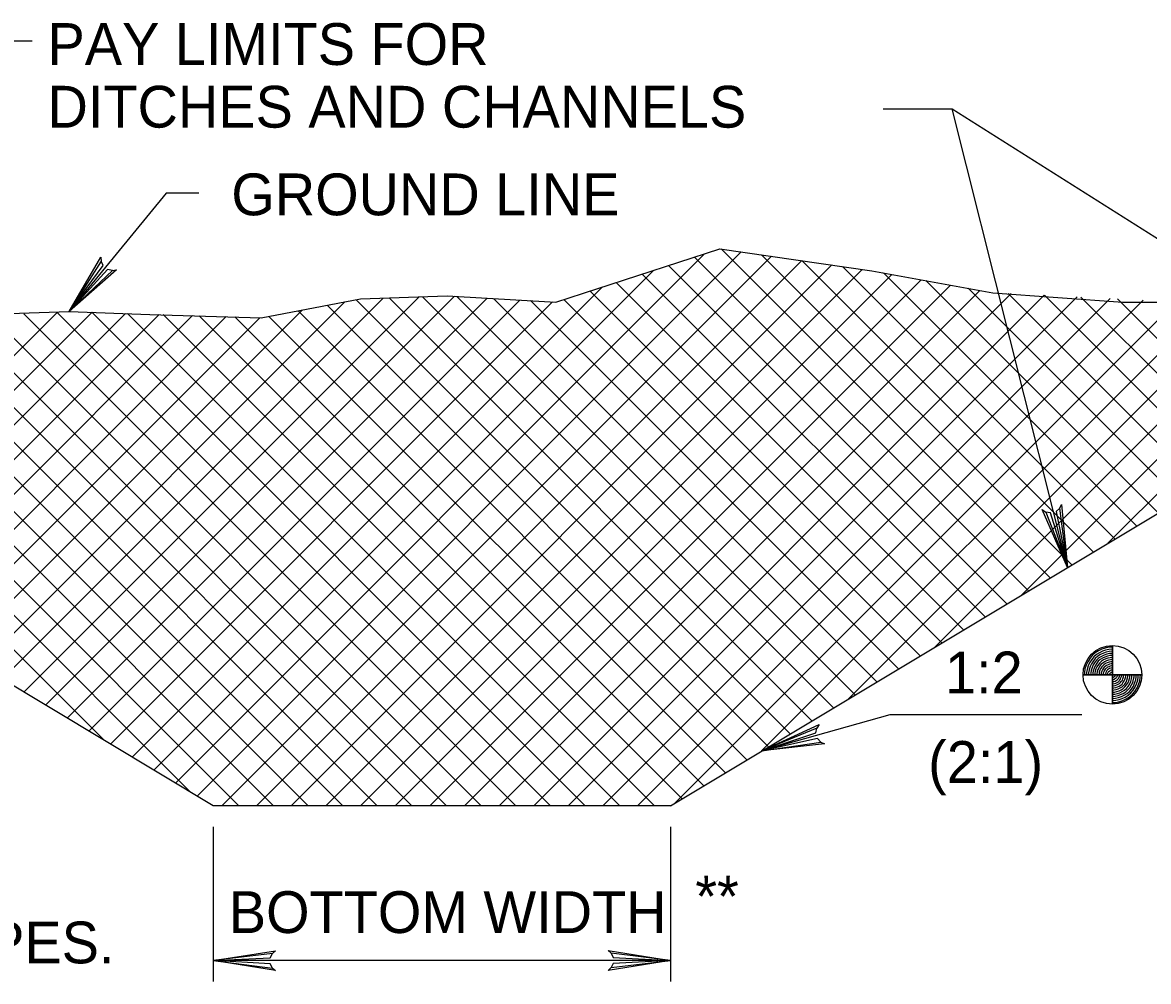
# Model space of a CAD drawing. Extents: x 240 to 1147, y 662 to 1256.
# Drawn here: x 810.7 to 896.9, y 1107.4 to 1180.9 of the extents above; entities that cross this region are included whole.
import ezdxf

# ---------------------------------------------------------------- set-up
doc = ezdxf.new("R2010")
doc.units = 0
for name, color, linetype in [('1', 7, 'Continuous'), ('2', 7, 'Continuous'), ('3', 7, 'Continuous')]:
    doc.layers.add(name, color=color, linetype=linetype)

msp = doc.modelspace()

# ---------------------------------------------------------------- linework, layer by layer
at = {"layer": '1'}
for points in [[(817.53525, 1161.876125), (817.17275, 1161.955125), (814.21425, 1158.728125), (817.53525, 1161.876125), (817.83725, 1161.930125), (814.21425, 1158.728125), (816.8185, 1162.242625), (816.6685, 1162.571875), (814.21425, 1158.728125), (816.656, 1162.898875), (816.6685, 1162.571875)], [(890.064, 1143.673375), (889.7885, 1143.426625), (890.658, 1139.136375), (890.064, 1143.673375), (890.19925, 1143.948875), (890.658, 1139.136375), (889.34825, 1143.308125), (888.9925, 1143.381125), (890.658, 1139.136375), (888.721, 1143.564375), (888.9925, 1143.381125)], [(871.77475, 1125.771875), (871.52275, 1126.042625), (867.24975, 1125.090625), (871.77475, 1125.771875), (872.054, 1125.642625), (867.24975, 1125.090625), (871.3955, 1126.482375), (871.46025, 1126.838625), (867.24975, 1125.090625), (871.63925, 1127.113625), (871.46025, 1126.838625)], [(829.7935, 1108.471875), (829.62475, 1108.801125), (825.254, 1109.042625), (829.7935, 1108.471875), (830.02675, 1108.273875), (825.254, 1109.042625), (829.6205, 1109.259375), (829.781, 1109.584375), (825.254, 1109.042625), (830.02675, 1109.801125), (829.781, 1109.584375)], [(855.71225, 1109.611375), (855.881, 1109.284375), (860.254, 1109.042625), (855.71225, 1109.611375), (855.479, 1109.811375), (860.254, 1109.042625), (855.88525, 1108.826125), (855.72675, 1108.501125), (860.254, 1109.042625), (855.479, 1108.284375), (855.72675, 1108.501125)]]:
    msp.add_lwpolyline(points, dxfattribs=at)
at = {"layer": '2'}
for p, q in [((876.54625, 1174.249125), (881.8395, 1174.249125)), ((881.8395, 1174.249125), (914.608, 1153.505125)), ((822.36025, 1122.630125), (862.879, 1163.148875)), ((824.0165, 1121.634375), (865.67475, 1163.294875)), ((825.92475, 1120.892625), (867.9915, 1162.959375)), ((887.66425, 1137.338625), (862.106, 1162.896875)), ((889.3205, 1138.334375), (864.13925, 1163.515625)), ((890.979, 1139.328125), (867.23725, 1163.067625)), ((828.57675, 1120.892625), (870.31025, 1162.623875)), ((831.229, 1120.892625), (872.62675, 1162.290625)), ((886.006, 1136.344875), (860.104, 1162.248875)), ((892.63525, 1140.321875), (870.33725, 1162.619875)), ((894.2935, 1141.317625), (873.43725, 1162.171875)), ((820.70175, 1123.623875), (858.954, 1161.873875)), ((833.881, 1120.892625), (874.9435, 1161.955125)), ((836.533, 1120.892625), (877.21025, 1161.569875)), ((884.34975, 1135.351125), (858.10175, 1161.598875)), ((895.94975, 1142.311375), (876.57475, 1161.686375)), ((819.0435, 1124.617625), (855.02675, 1160.601125)), ((839.183, 1120.892625), (879.454, 1161.163625)), ((841.83525, 1120.892625), (881.69775, 1160.755125)), ((844.48725, 1120.892625), (883.9435, 1160.348875)), ((882.6915, 1134.355125), (856.09975, 1160.948875)), ((897.608, 1143.305125), (879.81425, 1161.096875)), ((899.26425, 1144.298875), (883.056, 1160.509375)), ((887.129, 1137.017625), (910.61025, 1160.498875)), ((893.758, 1140.994875), (913.67675, 1160.913625)), ((807.4435, 1131.578125), (835.32475, 1159.461375)), ((809.09975, 1130.584375), (838.2685, 1159.751125)), ((810.758, 1129.590625), (841.0185, 1159.851125)), ((812.4165, 1128.594875), (843.7165, 1159.896875)), ((814.07275, 1127.601125), (846.22275, 1159.753125)), ((815.729, 1126.607375), (848.731, 1159.607375)), ((817.38725, 1125.611375), (851.23725, 1159.461375)), ((869.433, 1126.401125), (836.206, 1159.628125)), ((871.0915, 1127.394875), (838.7185, 1159.767625)), ((872.74775, 1128.390625), (841.279, 1159.861375)), ((874.406, 1129.384375), (843.904, 1159.886375)), ((876.06225, 1130.378125), (846.7185, 1159.723875)), ((847.13925, 1120.892625), (886.3455, 1160.098875)), ((877.7205, 1131.373875), (849.533, 1159.561375)), ((849.7915, 1120.892625), (888.8705, 1159.971875)), ((879.37675, 1132.367625), (852.0955, 1159.648875)), ((852.4415, 1120.892625), (891.3955, 1159.846875)), ((881.03525, 1133.361375), (854.09775, 1160.298875)), ((855.0935, 1120.892625), (893.92275, 1159.721875)), ((857.7455, 1120.892625), (896.44775, 1159.594875)), ((860.61225, 1121.107375), (898.97475, 1159.469875)), ((867.2415, 1125.086375), (901.831, 1159.676125)), ((873.8705, 1129.063625), (904.758, 1159.948875)), ((880.49975, 1133.040625), (907.683, 1160.223875)), ((900.92275, 1145.294875), (886.106, 1160.109375)), ((902.579, 1146.288625), (888.8955, 1159.971875)), ((904.23725, 1147.282375), (891.68725, 1159.832375)), ((905.8935, 1148.278125), (894.47675, 1159.692625)), ((816.8935, 1125.909375), (784.07275, 1158.728125)), ((823.5205, 1121.932375), (786.72475, 1158.728125)), ((827.21225, 1120.892625), (789.37675, 1158.728125)), ((829.86425, 1120.892625), (792.029, 1158.728125)), ((794.18525, 1139.534375), (813.33725, 1158.686375)), ((795.8435, 1138.538625), (815.97475, 1158.671875)), ((797.49975, 1137.544875), (818.5415, 1158.586375)), ((805.78725, 1132.573875), (832.054, 1158.840625)), ((851.07675, 1120.892625), (813.28525, 1158.684375)), ((853.729, 1120.892625), (815.94975, 1158.671875)), ((866.1185, 1124.411375), (831.74975, 1158.782375)), ((867.77675, 1125.407375), (833.979, 1159.205125)), ((832.5165, 1120.892625), (794.87275, 1158.534375)), ((835.1685, 1120.892625), (797.91025, 1158.151125)), ((799.158, 1136.551125), (821.11025, 1158.503125)), ((837.8185, 1120.892625), (800.629, 1158.084375)), ((800.81425, 1135.555125), (823.679, 1158.419875)), ((802.47275, 1134.561375), (826.2455, 1158.336375)), ((840.4705, 1120.892625), (803.16025, 1158.203125)), ((804.129, 1133.567625), (828.81425, 1158.253125)), ((843.12275, 1120.892625), (805.6915, 1158.323875)), ((845.77475, 1120.892625), (808.22275, 1158.444875)), ((848.42475, 1120.892625), (810.754, 1158.563625)), ((856.381, 1120.892625), (818.6915, 1158.582375)), ((859.033, 1120.892625), (821.431, 1158.492625)), ((861.14775, 1121.430125), (824.17275, 1158.403125)), ((862.804, 1122.423875), (826.91425, 1158.313625)), ((864.46225, 1123.417625), (829.5205, 1158.359375)), ((825.254, 1120.892625), (784.52275, 1145.330125)), ((860.254, 1120.892625), (900.98525, 1145.330125)), ((894.0935, 1128.669875), (894.0935, 1133.161375)), ((894.0935, 1133.159375), (894.0935, 1128.669875)), ((894.0955, 1128.669875), (894.0955, 1133.161375)), ((894.0955, 1133.159375), (894.0955, 1128.669875)), ((896.33725, 1130.915625), (891.84775, 1130.915625)), ((896.33725, 1130.913625), (891.84775, 1130.913625)), ((891.84975, 1130.915625), (896.33925, 1130.915625)), ((891.84975, 1130.913625), (896.33925, 1130.913625)), ((860.254, 1120.892625), (825.254, 1120.892625)), ((825.254, 1119.292625), (825.254, 1107.442625)), ((860.254, 1119.292625), (860.254, 1107.442625)), ((860.254, 1109.042625), (825.254, 1109.042625))]:
    msp.add_line(p, q, dxfattribs=at)
for points in [[(811.401, 1179.421875), (810.55175, 1179.421875), (808.05175, 1179.421875), (794.56225, 1139.307375)], [(890.658, 1139.136375), (881.8395, 1174.249125)], [(824.1455, 1167.786375), (821.6455, 1167.786375), (814.21425, 1158.728125)], [(759.52275, 1160.330125), (764.156, 1160.167625), (769.37675, 1160.167625), (776.4955, 1159.688625), (783.37675, 1158.728125), (793.3415, 1158.728125), (799.03725, 1158.009375), (807.3415, 1158.488625), (814.22275, 1158.728125), (820.3915, 1158.488625), (828.933, 1158.248875), (836.52675, 1159.688625), (843.1705, 1159.928125), (851.47475, 1159.448875), (864.05175, 1163.528125), (875.679, 1161.848875), (884.933, 1160.167625), (894.89775, 1159.448875), (899.406, 1159.448875), (912.2185, 1160.648875), (921.47275, 1162.328125), (925.98525, 1160.330125)], [(894.08725, 1133.040625), (893.79775, 1133.021875), (893.531, 1132.953125), (893.283, 1132.873875), (893.02675, 1132.751125), (892.78525, 1132.594875), (892.556, 1132.403125), (892.381, 1132.188625), (892.206, 1131.919875), (892.08925, 1131.657375), (891.99775, 1131.365625), (891.958, 1131.105125), (891.954, 1130.907375)], [(894.08725, 1132.880125), (893.82275, 1132.863625), (893.57475, 1132.801125), (893.3435, 1132.726125), (893.106, 1132.611375), (892.879, 1132.465625), (892.6705, 1132.290625), (892.51025, 1132.092625), (892.3455, 1131.844875), (892.23925, 1131.601125), (892.154, 1131.328125), (892.1165, 1131.092625), (892.11225, 1130.907375)], [(894.08725, 1132.719875), (893.84775, 1132.705125), (893.6185, 1132.646875), (893.40175, 1132.578125), (893.183, 1132.471875), (892.97275, 1132.336375), (892.78525, 1132.178125), (892.63925, 1131.998875), (892.48725, 1131.767625), (892.38925, 1131.544875), (892.31025, 1131.292625), (892.27675, 1131.078125), (892.27275, 1130.907375)], [(894.08725, 1132.561375), (893.87275, 1132.546875), (893.66425, 1132.494875), (893.46225, 1132.430125), (893.26225, 1132.332375), (893.0685, 1132.209375), (892.89975, 1132.065625), (892.7685, 1131.905125), (892.62675, 1131.690625), (892.53725, 1131.488625), (892.46425, 1131.257375), (892.43525, 1131.063625), (892.431, 1130.907375)], [(894.08725, 1132.401125), (893.89775, 1132.388625), (893.708, 1132.340625), (893.52275, 1132.280125), (893.33925, 1132.192625), (893.16225, 1132.080125), (893.01425, 1131.953125), (892.89775, 1131.809375), (892.7685, 1131.615625), (892.68725, 1131.432375), (892.6205, 1131.219875), (892.5955, 1131.048875), (892.5915, 1130.907375)], [(894.08725, 1132.240625), (893.92275, 1132.230125), (893.75175, 1132.188625), (893.581, 1132.132375), (893.4185, 1132.053125), (893.258, 1131.951125), (893.12675, 1131.842625), (893.02475, 1131.715625), (892.908, 1131.538625), (892.83725, 1131.376125), (892.77675, 1131.184375), (892.754, 1131.036375), (892.75175, 1130.907375)], [(894.08725, 1132.080125), (893.94775, 1132.071875), (893.7955, 1132.034375), (893.63925, 1131.984375), (893.4955, 1131.913625), (893.35175, 1131.821875), (893.2415, 1131.730125), (893.154, 1131.621875), (893.04975, 1131.461375), (892.98725, 1131.319875), (892.933, 1131.148875), (892.91225, 1131.021875), (892.91025, 1130.907375)], [(894.08725, 1131.921875), (893.9705, 1131.915625), (893.83925, 1131.880125), (893.69975, 1131.836375), (893.57275, 1131.773875), (893.44775, 1131.692625), (893.356, 1131.617625), (893.283, 1131.526125), (893.18925, 1131.386375), (893.13525, 1131.263625), (893.08725, 1131.111375), (893.07275, 1131.007375), (893.0705, 1130.907375)], [(894.08725, 1131.761375), (893.9955, 1131.757375), (893.88525, 1131.728125), (893.76025, 1131.688625), (893.65175, 1131.634375), (893.5415, 1131.565625), (893.4705, 1131.505125), (893.41225, 1131.432375), (893.331, 1131.309375), (893.28525, 1131.207375), (893.2435, 1131.076125), (893.231, 1130.994875), (893.229, 1130.907375)], [(894.08725, 1131.603125), (894.0205, 1131.598875), (893.929, 1131.573875), (893.8185, 1131.538625), (893.729, 1131.496875), (893.63725, 1131.436375), (893.58525, 1131.392625), (893.5415, 1131.338625), (893.4705, 1131.232375), (893.43525, 1131.151125), (893.39975, 1131.038625), (893.3915, 1130.980125), (893.38925, 1130.907375)], [(894.08725, 1131.442625), (894.0455, 1131.440625), (893.97275, 1131.421875), (893.879, 1131.390625), (893.808, 1131.357375), (893.731, 1131.307375), (893.69775, 1131.280125), (893.6685, 1131.244875), (893.61225, 1131.157375), (893.58525, 1131.094875), (893.556, 1131.003125), (893.54975, 1130.965625), (893.54775, 1130.907375)], [(893.7185, 1130.913625), (893.7185, 1130.930125), (893.733, 1130.984375), (893.758, 1131.061375), (893.783, 1131.115625), (893.8205, 1131.173875), (893.833, 1131.188625), (893.84975, 1131.203125), (893.9205, 1131.248875), (893.96225, 1131.267625), (894.03525, 1131.288625), (894.04775, 1131.290625), (894.0935, 1131.292625)], [(894.08725, 1131.121875), (894.06025, 1131.115625), (893.99775, 1131.094875), (893.96425, 1131.078125), (893.92475, 1131.053125), (893.8935, 1131.003125), (893.883, 1130.982375), (893.8685, 1130.932375), (893.8665, 1130.907375)], [(894.04975, 1130.907375), (894.04975, 1130.938625), (894.054, 1130.955125), (894.054, 1130.957375), (894.06225, 1130.965625), (894.06225, 1130.965625), (894.079, 1130.976125), (894.081, 1130.978125)], [(894.4705, 1130.915625), (894.4685, 1130.898875), (894.456, 1130.844875), (894.431, 1130.767625), (894.404, 1130.715625), (894.3665, 1130.655125), (894.356, 1130.642625), (894.33725, 1130.626125), (894.2685, 1130.580125), (894.22675, 1130.563625), (894.154, 1130.540625), (894.13925, 1130.538625), (894.0955, 1130.536375)], [(894.10175, 1128.790625), (894.38925, 1128.807375), (894.658, 1128.876125), (894.904, 1128.955125), (895.16025, 1129.078125), (895.404, 1129.234375), (895.631, 1129.426125), (895.806, 1129.642625), (895.983, 1129.909375), (896.09775, 1130.173875), (896.18925, 1130.463625), (896.229, 1130.723875), (896.23525, 1130.921875)], [(894.10175, 1128.948875), (894.3665, 1128.965625), (894.61425, 1129.028125), (894.8455, 1129.103125), (895.083, 1129.217625), (895.31025, 1129.363625), (895.5165, 1129.538625), (895.679, 1129.736375), (895.8415, 1129.986375), (895.94975, 1130.228125), (896.03525, 1130.501125), (896.0705, 1130.736375), (896.07475, 1130.921875)], [(894.10175, 1129.109375), (894.3415, 1129.123875), (894.5685, 1129.182375), (894.78525, 1129.253125), (895.004, 1129.357375), (895.21425, 1129.492625), (895.404, 1129.651125), (895.54975, 1129.830125), (895.70175, 1130.061375), (895.79975, 1130.284375), (895.879, 1130.536375), (895.91225, 1130.751125), (895.9165, 1130.921875)], [(894.10175, 1129.269875), (894.3165, 1129.282375), (894.52475, 1129.334375), (894.72675, 1129.401125), (894.92675, 1129.496875), (895.1205, 1129.621875), (895.28925, 1129.763625), (895.4205, 1129.923875), (895.56025, 1130.138625), (895.64975, 1130.340625), (895.72275, 1130.573875), (895.75175, 1130.765625), (895.756, 1130.921875)], [(894.10175, 1129.428125), (894.2915, 1129.440625), (894.481, 1129.488625), (894.6665, 1129.548875), (894.84775, 1129.636375), (895.02475, 1129.748875), (895.17475, 1129.876125), (895.2915, 1130.019875), (895.4205, 1130.215625), (895.49975, 1130.396875), (895.5665, 1130.609375), (895.5935, 1130.780125), (895.59775, 1130.921875)], [(894.10175, 1129.588625), (894.2665, 1129.598875), (894.43725, 1129.642625), (894.608, 1129.696875), (894.7705, 1129.776125), (894.931, 1129.878125), (895.06025, 1129.988625), (895.16225, 1130.113625), (895.279, 1130.290625), (895.35175, 1130.453125), (895.41225, 1130.644875), (895.43525, 1130.792625), (895.43725, 1130.921875)], [(894.10175, 1129.748875), (894.2415, 1129.757375), (894.3935, 1129.794875), (894.54775, 1129.844875), (894.6935, 1129.915625), (894.83525, 1130.007375), (894.9455, 1130.101125), (895.03525, 1130.207375), (895.13925, 1130.367625), (895.20175, 1130.509375), (895.256, 1130.682375), (895.27475, 1130.807375), (895.27675, 1130.921875)], [(894.10175, 1129.907375), (894.2165, 1129.915625), (894.34775, 1129.948875), (894.48725, 1129.992625), (894.61425, 1130.055125), (894.7415, 1130.136375), (894.833, 1130.211375), (894.906, 1130.303125), (894.99775, 1130.444875), (895.05175, 1130.565625), (895.09975, 1130.717625), (895.1165, 1130.821875), (895.1185, 1130.921875)], [(894.10175, 1130.067625), (894.1915, 1130.073875), (894.304, 1130.101125), (894.429, 1130.142625), (894.53725, 1130.194875), (894.6455, 1130.263625), (894.7185, 1130.323875), (894.77675, 1130.396875), (894.858, 1130.519875), (894.90175, 1130.621875), (894.9435, 1130.755125), (894.956, 1130.836375), (894.958, 1130.921875)], [(894.10175, 1130.228125), (894.1665, 1130.232375), (894.26025, 1130.255125), (894.3685, 1130.290625), (894.458, 1130.334375), (894.55175, 1130.392625), (894.604, 1130.436375), (894.64775, 1130.490625), (894.7165, 1130.596875), (894.754, 1130.678125), (894.78925, 1130.790625), (894.79775, 1130.848875), (894.79975, 1130.921875)], [(894.10175, 1130.386375), (894.1415, 1130.388625), (894.2165, 1130.409375), (894.31025, 1130.438625), (894.381, 1130.473875), (894.458, 1130.521875), (894.48925, 1130.548875), (894.5185, 1130.584375), (894.57675, 1130.673875), (894.604, 1130.734375), (894.633, 1130.826125), (894.63925, 1130.863625), (894.63925, 1130.921875)], [(894.10175, 1130.707375), (894.12675, 1130.715625), (894.1915, 1130.734375), (894.22475, 1130.751125), (894.26225, 1130.776125), (894.2955, 1130.826125), (894.304, 1130.846875), (894.3205, 1130.896875), (894.3205, 1130.921875)], [(894.13925, 1130.923875), (894.13725, 1130.892625), (894.13525, 1130.873875), (894.133, 1130.873875), (894.12675, 1130.863625), (894.12475, 1130.863625), (894.108, 1130.853125), (894.108, 1130.853125)], [(891.7475, 1127.853125), (877.0685, 1127.853125), (867.24975, 1125.090625)]]:
    msp.add_lwpolyline(points, dxfattribs=at)
for centre in [(894.093262, 1130.915563), (894.093262, 1130.913969), (894.09492, 1130.915563), (894.09492, 1130.913969)]:
    msp.add_circle(centre, 2.24484, dxfattribs=at)

# ---------------------------------------------------------------- texts
at = {"layer": '1'}
msp.add_text('(2:1)', height=3.1999995, dxfattribs=at).set_placement((879.99075, 1122.645625))
at = {"layer": '3'}
for s, height, p in [('PAY LIMITS FOR', 3.1999875, (812.5685, 1177.603125)), ('DITCHES AND CHANNELS', 3.1999875, (812.5685, 1172.805125)), ('GROUND LINE', 3.1999875, (826.63925, 1166.094875)), ('1:2', 3.1999995, (881.27875, 1129.494375)), ('**', 3.1999875, (862.16425, 1112.355125)), ('BOTTOM WIDTH', 3.1999875, (826.44775, 1111.151125)), ('SEE ROUNDING OF CUT SLOPES.', 3.1999875, (748.02925, 1108.829125))]:
    msp.add_text(s, height=height, dxfattribs=at).set_placement(p)

doc.saveas('drawing.dxf')
